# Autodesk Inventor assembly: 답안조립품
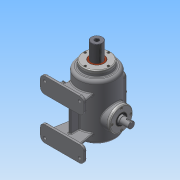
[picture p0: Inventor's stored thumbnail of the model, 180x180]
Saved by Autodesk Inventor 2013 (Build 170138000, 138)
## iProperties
Created: 2016-06
Part Number: 답안조립품
Document SubType Name: Assembly
Designer: Administrator
Mass: 8192.43 g
Surface Area: 4241.77 cm^2
Volume: 1855.48 cm^3
Density: 4.41526 g/cm^3
Author: Administrator
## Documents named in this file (15)
- C:\Users\Administrator\Desktop\Manufacturing1급-김길수\공용부품\답안조립품.iam
- C:\Users\Administrator\Desktop\Manufacturing1급-김길수\공용부품\본체.ipt
- C:\Users\Administrator\Desktop\Manufacturing1급-김길수\공용부품\슬라이드.ipt
- C:\Users\Administrator\Desktop\Manufacturing1급-김길수\공용부품\가변스프링.ipt
- C:\Users\Administrator\Desktop\Manufacturing1급-김길수\공용부품\부시.ipt
- C:\Users\Administrator\Desktop\Manufacturing1급-김길수\공용부품\슬라이드 커버.ipt
- C:\Users\Administrator\Desktop\Manufacturing1급-김길수\공용부품\볼트 M4x0.7.ipt
- C:\Users\Administrator\Desktop\Manufacturing1급-김길수\공용부품\베어링 6205.ipt
- 베어링 6205.ipt
- C:\Users\Administrator\Desktop\Manufacturing1급-김길수\공용부품\축 커버.ipt
- C:\Users\Administrator\Desktop\Manufacturing1급-김길수\공용부품\오일실.ipt
- 오일실.ipt
- C:\Users\Administrator\Desktop\Manufacturing1급-김길수\공용부품\편심축.ipt
- C:\Users\Administrator\Desktop\Manufacturing1급-김길수\공용부품\육각머리볼트 M4.ipt
- C:\Users\Administrator\Desktop\Manufacturing1급-김길수\공용부품\상부커버.ipt
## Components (13 placed, 2 different names)
1. 가변스프링:1 — 각도:6
2. M4x0.7:1
3. M4x0.7:3
4. M4x0.7:4
5. M4x0.7:5
6. M4x0.7:2
7. M4x0.7:6
8. M4x0.7:7
9. M4x0.7:8
10. M4x0.7:9
11. M4x0.7:10
12. M4x0.7:11
13. M4x0.7:12
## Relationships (1: Angle 1)
- 각도:6 [Angle]: 가변스프링:1
